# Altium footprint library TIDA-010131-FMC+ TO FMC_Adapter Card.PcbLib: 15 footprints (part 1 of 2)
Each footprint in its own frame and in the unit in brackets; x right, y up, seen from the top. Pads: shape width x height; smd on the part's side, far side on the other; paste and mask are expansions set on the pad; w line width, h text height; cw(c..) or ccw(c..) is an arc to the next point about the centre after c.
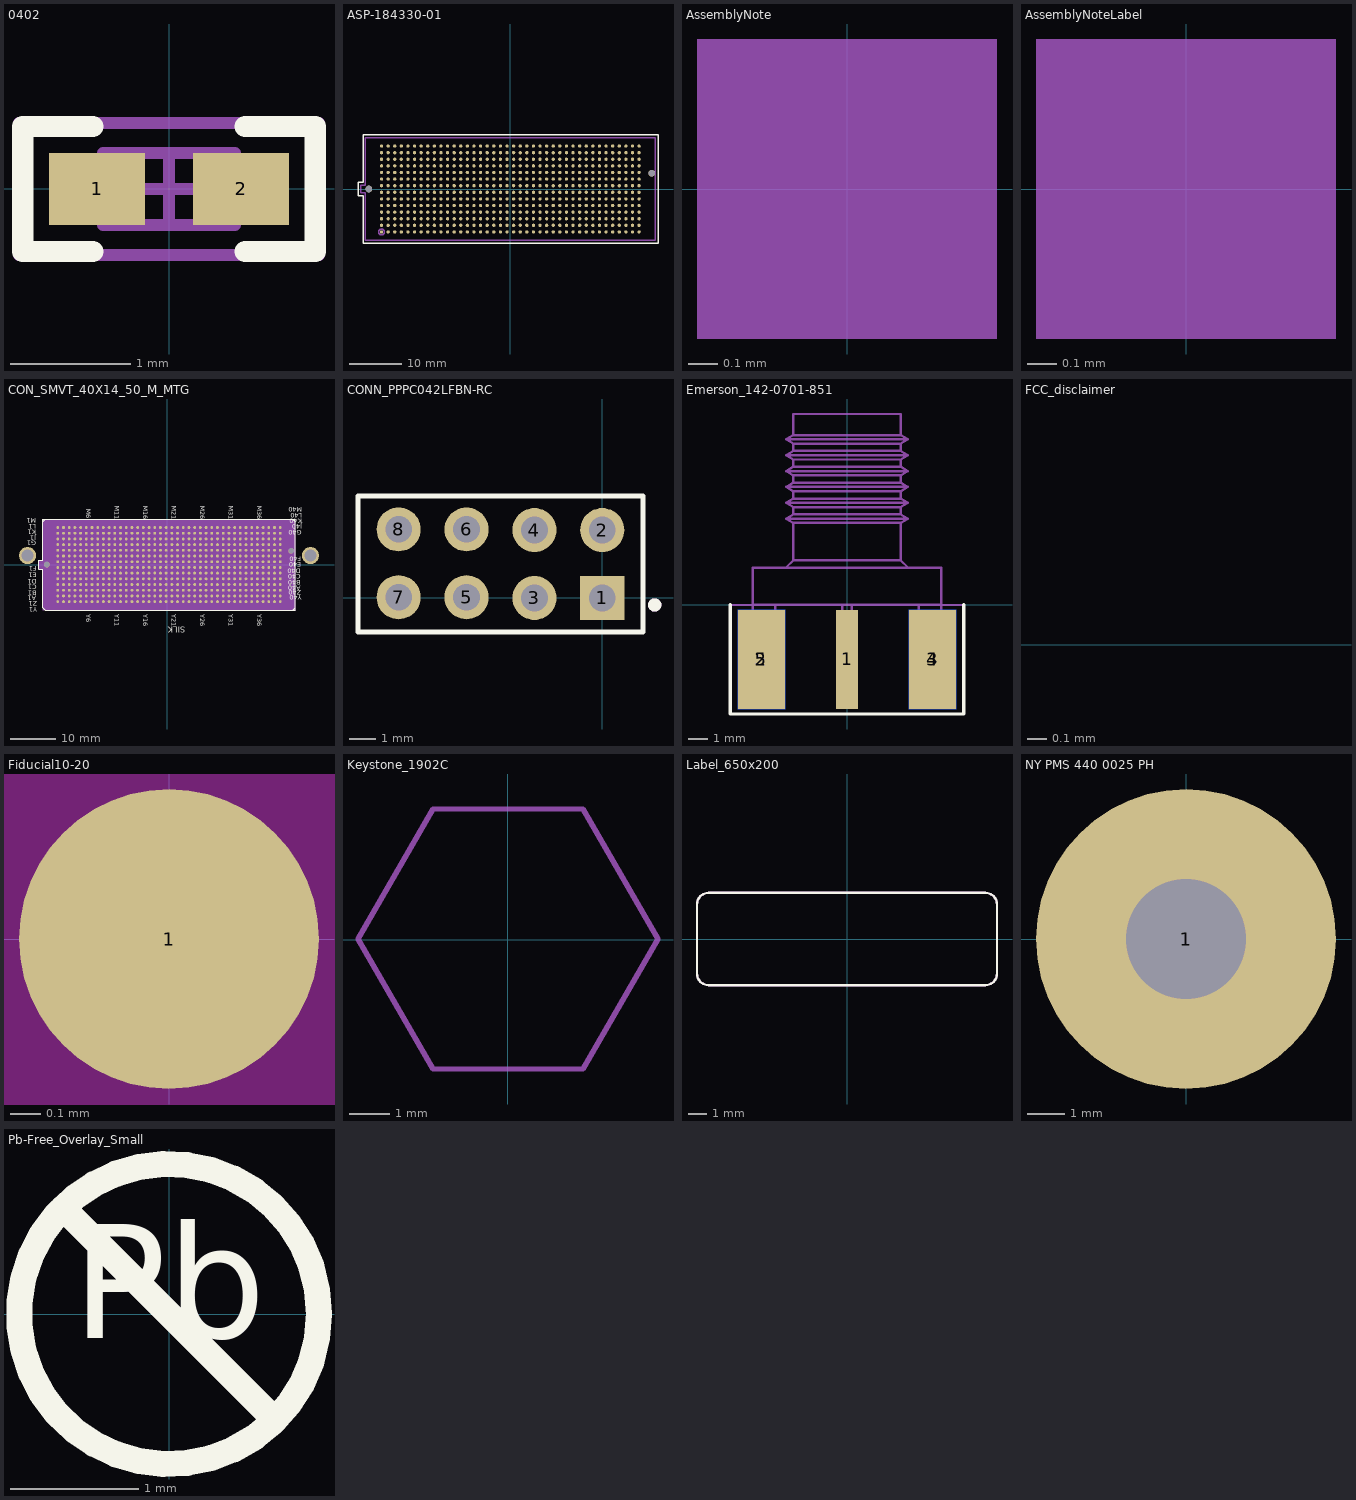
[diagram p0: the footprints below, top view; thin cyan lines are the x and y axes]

## 0402 [mm] "0402 from SM-752 data"
height 0.6
pads (2):
  rect 0.8x0.6 smd: 1(-0.6,0) 2(0.6,0)
Top Overlay:
  lines w0.178: -0.635,-0.521 -1.219,-0.521 -1.219,0.521 -0.635,0.521 ; 0.635,-0.521 1.219,-0.521 1.219,0.521 0.635,0.521
Mechanical 5:
  lines w0.1: -1.25,-0.55 1.25,-0.55 1.25,0.55 -1.25,0.55 -1.25,-0.55
  text ".Designator" at -1.117,-0.305 h0.61
Mechanical 13:
  lines w0.1: -0.35,-0.3 -0.35,0.3 ; 0.35,-0.3 0.35,0.3 ; -0.55,-0.3 -0.55,0.3 0.55,0.3 0.55,-0.3 -0.55,-0.3
Mechanical 15:
  lines w0.1: -0.3,0 0.3,0 ; 0,-0.3 0,0.3 ; -1.25,-0.55 -1.25,0.55 1.25,0.55 1.25,-0.55 -1.25,-0.55
3D body: height 0.6, standoff 0, extent -0.549,-0.299 -0.351,0.299
3D body: height 0.6, standoff 0, extent -0.349,-0.299 0.349,0.299
3D body: height 0.6, standoff 0, extent 0.351,-0.299 0.549,0.299

## ASP-184330-01 [mil]
height 375.2
pads (562):
  round 25 smd paste+5 mask+2: A1(-975,-225) A2(-925,-225) A3(-875,-225) A4(-825,-225) A5(-775,-225) A6(-725,-225) A7(-675,-225) A8(-625,-225) A9(-575,-225) A10(-525,-225) A11(-475,-225) A12(-425,-225) A13(-375,-225) A14(-325,-225) A15(-275,-225) A16(-225,-225) A17(-175,-225) A18(-125,-225) A19(-75,-225) A20(-25,-225) A21(25,-225) A22(75,-225) A23(125,-225) A24(175,-225) A25(225,-225) A26(275,-225) A27(325,-225) A28(375,-225) A29(425,-225) A30(475,-225) A31(525,-225) A32(575,-225) A33(625,-225) A34(675,-225) A35(725,-225) A36(775,-225) A37(825,-225) A38(875,-225) A39(925,-225) A40(975,-225) B1(-975,-175) B2(-925,-175) B3(-875,-175) B4(-825,-175) B5(-775,-175) B6(-725,-175) B7(-675,-175) B8(-625,-175) B9(-575,-175) B10(-525,-175) B11(-475,-175) B12(-425,-175) B13(-375,-175) B14(-325,-175) B15(-275,-175) B16(-225,-175) B17(-175,-175) B18(-125,-175) B19(-75,-175) B20(-25,-175) B21(25,-175) B22(75,-175) B23(125,-175) B24(175,-175) B25(225,-175) B26(275,-175) B27(325,-175) B28(375,-175) B29(425,-175) B30(475,-175) B31(525,-175) B32(575,-175) B33(625,-175) B34(675,-175) B35(725,-175) B36(775,-175) B37(825,-175) B38(875,-175) B39(925,-175) B40(975,-175) C1(-975,-125) C2(-925,-125) C3(-875,-125) C4(-825,-125) C5(-775,-125) C6(-725,-125) C7(-675,-125) C8(-625,-125) C9(-575,-125) C10(-525,-125) C11(-475,-125) C12(-425,-125) C13(-375,-125) C14(-325,-125) C15(-275,-125) C16(-225,-125) C17(-175,-125) C18(-125,-125) C19(-75,-125) C20(-25,-125) C21(25,-125) C22(75,-125) C23(125,-125) C24(175,-125) C25(225,-125) C26(275,-125) C27(325,-125) C28(375,-125) C29(425,-125) C30(475,-125) C31(525,-125) C32(575,-125) C33(625,-125) C34(675,-125) C35(725,-125) C36(775,-125) C37(825,-125) C38(875,-125) C39(925,-125) C40(975,-125) D1(-975,-75) D2(-925,-75) D3(-875,-75) D4(-825,-75) D5(-775,-75) D6(-725,-75) D7(-675,-75) D8(-625,-75) D9(-575,-75) D10(-525,-75) D11(-475,-75) D12(-425,-75) D13(-375,-75) D14(-325,-75) D15(-275,-75) D16(-225,-75) D17(-175,-75) D18(-125,-75) D19(-75,-75) D20(-25,-75) D21(25,-75) D22(75,-75) D23(125,-75) D24(175,-75) D25(225,-75) D26(275,-75) D27(325,-75) D28(375,-75) D29(425,-75) D30(475,-75) D31(525,-75) D32(575,-75) D33(625,-75) D34(675,-75) D35(725,-75) D36(775,-75) D37(825,-75) D38(875,-75) D39(925,-75) D40(975,-75) E1(-975,-25) E2(-925,-25) E3(-875,-25) E4(-825,-25) E5(-775,-25) E6(-725,-25) E7(-675,-25) E8(-625,-25) E9(-575,-25) E10(-525,-25) E11(-475,-25) E12(-425,-25) E13(-375,-25) E14(-325,-25) E15(-275,-25) E16(-225,-25) E17(-175,-25) E18(-125,-25) E19(-75,-25) E20(-25,-25) E21(25,-25) E22(75,-25) E23(125,-25) E24(175,-25) E25(225,-25) E26(275,-25) E27(325,-25) E28(375,-25) E29(425,-25) E30(475,-25) E31(525,-25) E32(575,-25) E33(625,-25) E34(675,-25) E35(725,-25) E36(775,-25) E37(825,-25) E38(875,-25) E39(925,-25) E40(975,-25) F1(-975,25) F2(-925,25) F3(-875,25) F4(-825,25) F5(-775,25) F6(-725,25) F7(-675,25) F8(-625,25) F9(-575,25) F10(-525,25) F11(-475,25) F12(-425,25) F13(-375,25) F14(-325,25) F15(-275,25) F16(-225,25) F17(-175,25) F18(-125,25) F19(-75,25) F20(-25,25) F21(25,25) F22(75,25) F23(125,25) F24(175,25) F25(225,25) F26(275,25) F27(325,25) F28(375,25) F29(425,25) F30(475,25) F31(525,25) F32(575,25) F33(625,25) F34(675,25) F35(725,25) F36(775,25) F37(825,25) F38(875,25) F39(925,25) F40(975,25) G1(-975,75) G2(-925,75) G3(-875,75) G4(-825,75) G5(-775,75) G6(-725,75) G7(-675,75) G8(-625,75) G9(-575,75) G10(-525,75) G11(-475,75) G12(-425,75) G13(-375,75) G14(-325,75) G15(-275,75) G16(-225,75) G17(-175,75) G18(-125,75) G19(-75,75) G20(-25,75) G21(25,75) G22(75,75) G23(125,75) G24(175,75) G25(225,75) G26(275,75) G27(325,75) G28(375,75) G29(425,75) G30(475,75) G31(525,75) G32(575,75) G33(625,75) G34(675,75) G35(725,75) G36(775,75) G37(825,75) G38(875,75) G39(925,75) G40(975,75) H1(-975,125) H2(-925,125) H3(-875,125) H4(-825,125) H5(-775,125) H6(-725,125) H7(-675,125) H8(-625,125) H9(-575,125) H10(-525,125) H11(-475,125) H12(-425,125) H13(-375,125) H14(-325,125) H15(-275,125) H16(-225,125) H17(-175,125) H18(-125,125) H19(-75,125) H20(-25,125) H21(25,125) H22(75,125) H23(125,125) H24(175,125) H25(225,125) H26(275,125) H27(325,125) H28(375,125) H29(425,125) H30(475,125) H31(525,125) H32(575,125) H33(625,125) H34(675,125) H35(725,125) H36(775,125) H37(825,125) H38(875,125) H39(925,125) H40(975,125) J1(-975,175) J2(-925,175) J3(-875,175) J4(-825,175) J5(-775,175) J6(-725,175) J7(-675,175) J8(-625,175) J9(-575,175) J10(-525,175) J11(-475,175) J12(-425,175) J13(-375,175) J14(-325,175) J15(-275,175) J16(-225,175) J17(-175,175) J18(-125,175) J19(-75,175) J20(-25,175) J21(25,175) J22(75,175) J23(125,175) J24(175,175) J25(225,175) J26(275,175) J27(325,175) J28(375,175) J29(425,175) J30(475,175) J31(525,175) J32(575,175) J33(625,175) J34(675,175) J35(725,175) J36(775,175) J37(825,175) J38(875,175) J39(925,175) J40(975,175) K1(-975,225) K2(-925,225) K3(-875,225) K4(-825,225) K5(-775,225) K6(-725,225) K7(-675,225) K8(-625,225) K9(-575,225) K10(-525,225) K11(-475,225) K12(-425,225) K13(-375,225) K14(-325,225) K15(-275,225) K16(-225,225) K17(-175,225) K18(-125,225) K19(-75,225) K20(-25,225) K21(25,225) K22(75,225) K23(125,225) K24(175,225) K25(225,225) K26(275,225) K27(325,225) K28(375,225) K29(425,225) K30(475,225) K31(525,225) K32(575,225) K33(625,225) K34(675,225) K35(725,225) K36(775,225) K37(825,225) K38(875,225) K39(925,225) K40(975,225) L1(-975,275) L2(-925,275) L3(-875,275) L4(-825,275) L5(-775,275) L6(-725,275) L7(-675,275) L8(-625,275) L9(-575,275) L10(-525,275) L11(-475,275) L12(-425,275) L13(-375,275) L14(-325,275) L15(-275,275) L16(-225,275) L17(-175,275) L18(-125,275) L19(-75,275) L20(-25,275) L21(25,275) L22(75,275) L23(125,275) L24(175,275) L25(225,275) L26(275,275) L27(325,275) L28(375,275) L29(425,275) L30(475,275) L31(525,275) L32(575,275) L33(625,275) L34(675,275) L35(725,275) L36(775,275) L37(825,275) L38(875,275) L39(925,275) L40(975,275) M1(-975,325) M2(-925,325) M3(-875,325) M4(-825,325) M5(-775,325) M6(-725,325) M7(-675,325) M8(-625,325) M9(-575,325) M10(-525,325) M11(-475,325) M12(-425,325) M13(-375,325) M14(-325,325) M15(-275,325) M16(-225,325) M17(-175,325) M18(-125,325) M19(-75,325) M20(-25,325) M21(25,325) M22(75,325) M23(125,325) M24(175,325) M25(225,325) M26(275,325) M27(325,325) M28(375,325) M29(425,325) M30(475,325) M31(525,325) M32(575,325) M33(625,325) M34(675,325) M35(725,325) M36(775,325) M37(825,325) M38(875,325) M39(925,325) M40(975,325) Y1(-975,-325) Y2(-925,-325) Y3(-875,-325) Y4(-825,-325) Y5(-775,-325) Y6(-725,-325) Y7(-675,-325) Y8(-625,-325) Y9(-575,-325) Y10(-525,-325) Y11(-475,-325) Y12(-425,-325) Y13(-375,-325) Y14(-325,-325) Y15(-275,-325) Y16(-225,-325) Y17(-175,-325) Y18(-125,-325) Y19(-75,-325) Y20(-25,-325) Y21(25,-325) Y22(75,-325) Y23(125,-325) Y24(175,-325) Y25(225,-325) Y26(275,-325) Y27(325,-325) Y28(375,-325) Y29(425,-325) Y30(475,-325) Y31(525,-325) Y32(575,-325) Y33(625,-325) Y34(675,-325) Y35(725,-325) Y36(775,-325) Y37(825,-325) Y38(875,-325) Y39(925,-325) Y40(975,-325) Z1(-975,-275) Z2(-925,-275) Z3(-875,-275) Z4(-825,-275) Z5(-775,-275) Z6(-725,-275) Z7(-675,-275) Z8(-625,-275) Z9(-575,-275) Z10(-525,-275) Z11(-475,-275) Z12(-425,-275) Z13(-375,-275) Z14(-325,-275) Z15(-275,-275) Z16(-225,-275) Z17(-175,-275) Z18(-125,-275) Z19(-75,-275) Z20(-25,-275) Z21(25,-275) Z22(75,-275) Z23(125,-275) Z24(175,-275) Z25(225,-275) Z26(275,-275) Z27(325,-275) Z28(375,-275) Z29(425,-275) Z30(475,-275) Z31(525,-275) Z32(575,-275) Z33(625,-275) Z34(675,-275) Z35(725,-275) Z36(775,-275) Z37(825,-275) Z38(875,-275) Z39(925,-275) Z40(975,-275)
  round 50 hole 50 unplated mask+10: MH1(-1070.5,0) MH2(1070.5,120)
Top Overlay:
  lines w10: -1153,-50 -1115,-50 -1115,-409 1118,-409 1118,409 -1115,409 -1115,50 -1153,50 -1153,-50
Mechanical 5:
  circle w10: c-975,-325 r22.36
  lines w10: -1133,-30 -1098,-30 -1098,-389 1098,-389 1098,389 -1098,389 -1098,30 -1133,30 -1133,-30
  text "J1" at 52.11,-0.07 h20

## AssemblyNote [mil] "Assembly Note"
Mechanical 5:
  rectangle: -20,-20 20,20
  text ".Designator" at -165,-20 h25

## AssemblyNoteLabel [mil] "Assembly Note for PCB Labels"
Mechanical 5:
  rectangle: -20,-20 20,20
  text ".Designator" at -165,-20 h25
  text "Install label in silkscreened box after final wash.  Text shall be 8 pt font.  Text shall be per the Label Table in the PDF schematic." at 45,-20 h25

## CON_SMVT_40X14_50_M_MTG [mil] "CON_SMVT_40X14_50_M_MTG"
pads (564):
  round 150 hole 106: " "(-1222.5,79) " "(1257.5,79)
  round 50 hole 50: " "(-1053,0) " "(1088,120)
  round 25 smd: A1(-957.5,-225) A2(-907.5,-225) A3(-857.5,-225) A4(-807.5,-225) A5(-757.5,-225) A6(-707.5,-225) A7(-657.5,-225) A8(-607.5,-225) A9(-557.5,-225) A10(-507.5,-225) A11(-457.5,-225) A12(-407.5,-225) A13(-357.5,-225) A14(-307.5,-225) A15(-257.5,-225) A16(-207.5,-225) A17(-157.5,-225) A18(-107.5,-225) A19(-57.5,-225) A20(-7.5,-225) A21(42.5,-225) A22(92.5,-225) A23(142.5,-225) A24(192.5,-225) A25(242.5,-225) A26(292.5,-225) A27(342.5,-225) A28(392.5,-225) A29(442.5,-225) A30(492.5,-225) A31(542.5,-225) A32(592.5,-225) A33(642.5,-225) A34(692.5,-225) A35(742.5,-225) A36(792.5,-225) A37(842.5,-225) A38(892.5,-225) A39(942.5,-225) A40(992.5,-225) B1(-957.5,-175) B2(-907.5,-175) B3(-857.5,-175) B4(-807.5,-175) B5(-757.5,-175) B6(-707.5,-175) B7(-657.5,-175) B8(-607.5,-175) B9(-557.5,-175) B10(-507.5,-175) B11(-457.5,-175) B12(-407.5,-175) B13(-357.5,-175) B14(-307.5,-175) B15(-257.5,-175) B16(-207.5,-175) B17(-157.5,-175) B18(-107.5,-175) B19(-57.5,-175) B20(-7.5,-175) B21(42.5,-175) B22(92.5,-175) B23(142.5,-175) B24(192.5,-175) B25(242.5,-175) B26(292.5,-175) B27(342.5,-175) B28(392.5,-175) B29(442.5,-175) B30(492.5,-175) B31(542.5,-175) B32(592.5,-175) B33(642.5,-175) B34(692.5,-175) B35(742.5,-175) B36(792.5,-175) B37(842.5,-175) B38(892.5,-175) B39(942.5,-175) B40(992.5,-175) C1(-957.5,-125) C2(-907.5,-125) C3(-857.5,-125) C4(-807.5,-125) C5(-757.5,-125) C6(-707.5,-125) C7(-657.5,-125) C8(-607.5,-125) C9(-557.5,-125) C10(-507.5,-125) C11(-457.5,-125) C12(-407.5,-125) C13(-357.5,-125) C14(-307.5,-125) C15(-257.5,-125) C16(-207.5,-125) C17(-157.5,-125) C18(-107.5,-125) C19(-57.5,-125) C20(-7.5,-125) C21(42.5,-125) C22(92.5,-125) C23(142.5,-125) C24(192.5,-125) C25(242.5,-125) C26(292.5,-125) C27(342.5,-125) C28(392.5,-125) C29(442.5,-125) C30(492.5,-125) C31(542.5,-125) C32(592.5,-125) C33(642.5,-125) C34(692.5,-125) C35(742.5,-125) C36(792.5,-125) C37(842.5,-125) C38(892.5,-125) C39(942.5,-125) C40(992.5,-125) D1(-957.5,-75) D2(-907.5,-75) D3(-857.5,-75) D4(-807.5,-75) D5(-757.5,-75) D6(-707.5,-75) D7(-657.5,-75) D8(-607.5,-75) D9(-557.5,-75) D10(-507.5,-75) D11(-457.5,-75) D12(-407.5,-75) D13(-357.5,-75) D14(-307.5,-75) D15(-257.5,-75) D16(-207.5,-75) D17(-157.5,-75) D18(-107.5,-75) D19(-57.5,-75) D20(-7.5,-75) D21(42.5,-75) D22(92.5,-75) D23(142.5,-75) D24(192.5,-75) D25(242.5,-75) D26(292.5,-75) D27(342.5,-75) D28(392.5,-75) D29(442.5,-75) D30(492.5,-75) D31(542.5,-75) D32(592.5,-75) D33(642.5,-75) D34(692.5,-75) D35(742.5,-75) D36(792.5,-75) D37(842.5,-75) D38(892.5,-75) D39(942.5,-75) D40(992.5,-75) E1(-957.5,-25) E2(-907.5,-25) E3(-857.5,-25) E4(-807.5,-25) E5(-757.5,-25) E6(-707.5,-25) E7(-657.5,-25) E8(-607.5,-25) E9(-557.5,-25) E10(-507.5,-25) E11(-457.5,-25) E12(-407.5,-25) E13(-357.5,-25) E14(-307.5,-25) E15(-257.5,-25) E16(-207.5,-25) E17(-157.5,-25) E18(-107.5,-25) E19(-57.5,-25) E20(-7.5,-25) E21(42.5,-25) E22(92.5,-25) E23(142.5,-25) E24(192.5,-25) E25(242.5,-25) E26(292.5,-25) E27(342.5,-25) E28(392.5,-25) E29(442.5,-25) E30(492.5,-25) E31(542.5,-25) E32(592.5,-25) E33(642.5,-25) E34(692.5,-25) E35(742.5,-25) E36(792.5,-25) E37(842.5,-25) E38(892.5,-25) E39(942.5,-25) E40(992.5,-25) F1(-957.5,25) F2(-907.5,25) F3(-857.5,25) F4(-807.5,25) F5(-757.5,25) F6(-707.5,25) F7(-657.5,25) F8(-607.5,25) F9(-557.5,25) F10(-507.5,25) F11(-457.5,25) F12(-407.5,25) F13(-357.5,25) F14(-307.5,25) F15(-257.5,25) F16(-207.5,25) F17(-157.5,25) F18(-107.5,25) F19(-57.5,25) F20(-7.5,25) F21(42.5,25) F22(92.5,25) F23(142.5,25) F24(192.5,25) F25(242.5,25) F26(292.5,25) F27(342.5,25) F28(392.5,25) F29(442.5,25) F30(492.5,25) F31(542.5,25) F32(592.5,25) F33(642.5,25) F34(692.5,25) F35(742.5,25) F36(792.5,25) F37(842.5,25) F38(892.5,25) F39(942.5,25) F40(992.5,25) G1(-957.5,75) G2(-907.5,75) G3(-857.5,75) G4(-807.5,75) G5(-757.5,75) G6(-707.5,75) G7(-657.5,75) G8(-607.5,75) G9(-557.5,75) G10(-507.5,75) G11(-457.5,75) G12(-407.5,75) G13(-357.5,75) G14(-307.5,75) G15(-257.5,75) G16(-207.5,75) G17(-157.5,75) G18(-107.5,75) G19(-57.5,75) G20(-7.5,75) G21(42.5,75) G22(92.5,75) G23(142.5,75) G24(192.5,75) G25(242.5,75) G26(292.5,75) G27(342.5,75) G28(392.5,75) G29(442.5,75) G30(492.5,75) G31(542.5,75) G32(592.5,75) G33(642.5,75) G34(692.5,75) G35(742.5,75) G36(792.5,75) G37(842.5,75) G38(892.5,75) G39(942.5,75) G40(992.5,75) H1(-957.5,125) H2(-907.5,125) H3(-857.5,125) H4(-807.5,125) H5(-757.5,125) H6(-707.5,125) H7(-657.5,125) H8(-607.5,125) H9(-557.5,125) H10(-507.5,125) H11(-457.5,125) H12(-407.5,125) H13(-357.5,125) H14(-307.5,125) H15(-257.5,125) H16(-207.5,125) H17(-157.5,125) H18(-107.5,125) H19(-57.5,125) H20(-7.5,125) H21(42.5,125) H22(92.5,125) H23(142.5,125) H24(192.5,125) H25(242.5,125) H26(292.5,125) H27(342.5,125) H28(392.5,125) H29(442.5,125) H30(492.5,125) H31(542.5,125) H32(592.5,125) H33(642.5,125) H34(692.5,125) H35(742.5,125) H36(792.5,125) H37(842.5,125) H38(892.5,125) H39(942.5,125) H40(992.5,125) J1(-957.5,175) J2(-907.5,175) J3(-857.5,175) J4(-807.5,175) J5(-757.5,175) J6(-707.5,175) J7(-657.5,175) J8(-607.5,175) J9(-557.5,175) J10(-507.5,175) J11(-457.5,175) J12(-407.5,175) J13(-357.5,175) J14(-307.5,175) J15(-257.5,175) J16(-207.5,175) J17(-157.5,175) J18(-107.5,175) J19(-57.5,175) J20(-7.5,175) J21(42.5,175) J22(92.5,175) J23(142.5,175) J24(192.5,175) J25(242.5,175) J26(292.5,175) J27(342.5,175) J28(392.5,175) J29(442.5,175) J30(492.5,175) J31(542.5,175) J32(592.5,175) J33(642.5,175) J34(692.5,175) J35(742.5,175) J36(792.5,175) J37(842.5,175) J38(892.5,175) J39(942.5,175) J40(992.5,175) K1(-957.5,225) K2(-907.5,225) K3(-857.5,225) K4(-807.5,225) K5(-757.5,225) K6(-707.5,225) K7(-657.5,225) K8(-607.5,225) K9(-557.5,225) K10(-507.5,225) K11(-457.5,225) K12(-407.5,225) K13(-357.5,225) K14(-307.5,225) K15(-257.5,225) K16(-207.5,225) K17(-157.5,225) K18(-107.5,225) K19(-57.5,225) K20(-7.5,225) K21(42.5,225) K22(92.5,225) K23(142.5,225) K24(192.5,225) K25(242.5,225) K26(292.5,225) K27(342.5,225) K28(392.5,225) K29(442.5,225) K30(492.5,225) K31(542.5,225) K32(592.5,225) K33(642.5,225) K34(692.5,225) K35(742.5,225) K36(792.5,225) K37(842.5,225) K38(892.5,225) K39(942.5,225) K40(992.5,225) L1(-957.5,275) L2(-907.5,275) L3(-857.5,275) L4(-807.5,275) L5(-757.5,275) L6(-707.5,275) L7(-657.5,275) L8(-607.5,275) L9(-557.5,275) L10(-507.5,275) L11(-457.5,275) L12(-407.5,275) L13(-357.5,275) L14(-307.5,275) L15(-257.5,275) L16(-207.5,275) L17(-157.5,275) L18(-107.5,275) L19(-57.5,275) L20(-7.5,275) L21(42.5,275) L22(92.5,275) L23(142.5,275) L24(192.5,275) L25(242.5,275) L26(292.5,275) L27(342.5,275) L28(392.5,275) L29(442.5,275) L30(492.5,275) L31(542.5,275) L32(592.5,275) L33(642.5,275) L34(692.5,275) L35(742.5,275) L36(792.5,275) L37(842.5,275) L38(892.5,275) L39(942.5,275) L40(992.5,275) M1(-957.5,325) M2(-907.5,325) M3(-857.5,325) M4(-807.5,325) M5(-757.5,325) M6(-707.5,325) M7(-657.5,325) M8(-607.5,325) M9(-557.5,325) M10(-507.5,325) M11(-457.5,325) M12(-407.5,325) M13(-357.5,325) M14(-307.5,325) M15(-257.5,325) M16(-207.5,325) M17(-157.5,325) M18(-107.5,325) M19(-57.5,325) M20(-7.5,325) M21(42.5,325) M22(92.5,325) M23(142.5,325) M24(192.5,325) M25(242.5,325) M26(292.5,325) M27(342.5,325) M28(392.5,325) M29(442.5,325) M30(492.5,325) M31(542.5,325) M32(592.5,325) M33(642.5,325) M34(692.5,325) M35(742.5,325) M36(792.5,325) M37(842.5,325) M38(892.5,325) M39(942.5,325) M40(992.5,325) Y1(-957.5,-325) Y2(-907.5,-325) Y3(-857.5,-325) Y4(-807.5,-325) Y5(-757.5,-325) Y6(-707.5,-325) Y7(-657.5,-325) Y8(-607.5,-325) Y9(-557.5,-325) Y10(-507.5,-325) Y11(-457.5,-325) Y12(-407.5,-325) Y13(-357.5,-325) Y14(-307.5,-325) Y15(-257.5,-325) Y16(-207.5,-325) Y17(-157.5,-325) Y18(-107.5,-325) Y19(-57.5,-325) Y20(-7.5,-325) Y21(42.5,-325) Y22(92.5,-325) Y23(142.5,-325) Y24(192.5,-325) Y25(242.5,-325) Y26(292.5,-325) Y27(342.5,-325) Y28(392.5,-325) Y29(442.5,-325) Y30(492.5,-325) Y31(542.5,-325) Y32(592.5,-325) Y33(642.5,-325) Y34(692.5,-325) Y35(742.5,-325) Y36(792.5,-325) Y37(842.5,-325) Y38(892.5,-325) Y39(942.5,-325) Y40(992.5,-325) Z1(-957.5,-275) Z2(-907.5,-275) Z3(-857.5,-275) Z4(-807.5,-275) Z5(-757.5,-275) Z6(-707.5,-275) Z7(-657.5,-275) Z8(-607.5,-275) Z9(-557.5,-275) Z10(-507.5,-275) Z11(-457.5,-275) Z12(-407.5,-275) Z13(-357.5,-275) Z14(-307.5,-275) Z15(-257.5,-275) Z16(-207.5,-275) Z17(-157.5,-275) Z18(-107.5,-275) Z19(-57.5,-275) Z20(-7.5,-275) Z21(42.5,-275) Z22(92.5,-275) Z23(142.5,-275) Z24(192.5,-275) Z25(242.5,-275) Z26(292.5,-275) Z27(342.5,-275) Z28(392.5,-275) Z29(442.5,-275) Z30(492.5,-275) Z31(542.5,-275) Z32(592.5,-275) Z33(642.5,-275) Z34(692.5,-275) Z35(742.5,-275) Z36(792.5,-275) Z37(842.5,-275) Z38(892.5,-275) Z39(942.5,-275) Z40(992.5,-275)
Top Overlay:
  lines w10: -1090.5,377 -1068.5,399 ; 1103.5,-399 1125.5,-377 ; 1103.5,399 1125.5,377 ; -1125.5,-40 -1125.5,40 -1090.5,40 -1090.5,399 1125.5,399 1125.5,-399 -1068.5,-399 -1090.5,-377 -1090.5,-40 -1125.5,-40
  text "D40" at 1173.5,-37 h40
  text "M36" at 792.5,515 h40
  text "M31" at 542.5,515 h40
  text "M26" at 292.5,515 h40
  text "M21" at 42.5,515 h40
  text "M16" at -207.5,515 h40
  text "M11" at -457.5,515 h40
  text "M6" at -707.5,490 h40
  text "Y36" at 792.5,-435 h40
  text "Y31" at 542.5,-435 h40
  text "Y26" at 292.5,-435 h40
  text "Y21" at 42.5,-435 h40
  text "Y16" at -207.5,-435 h40
  text "Y11" at -457.5,-435 h40
  text "D1" at -1142.5,-128 h40
  text "SILK" at 158.5,-545 h50
  text "C1" at -1142.5,-178 h40
  text "Y6" at -707.5,-435 h40
  text "C40" at 1173.5,-87 h40
  text "B1" at -1142.5,-228 h40
  text "Y1" at -1136.5,-374.33 h40
  text "B40" at 1173.5,-137 h40
  text "Y40" at 1179.5,-269.33 h40
  text "M40" at 1183.5,502 h40
  text "M1" at -1145.5,404 h40
  text "L40" at 1183.5,452 h40
  text "L1" at -1145.5,354 h40
  text "K40" at 1183.5,402 h40
  text "K1" at -1145.5,304 h40
  text "J40" at 1183.5,352 h40
  text "J1" at -1145.5,254 h40
  text "E1" at -1140.5,-71.33 h40
  text "E40" at 1176.5,19.67 h40
  text "F40" at 1178.5,68 h40
  text "G40" at 1180.5,301.67 h40
  text "F1" at -1140.5,-14 h40
  text "G1" at -1144.5,207.67 h40
  text "Z40" at 1177.5,-227 h40
  text "Z1" at -1136.5,-323 h40
  text "A40" at 1172.5,-185 h40
  text "A1" at -1144.5,-273 h40
Bottom Overlay:
  text "M1" at -1057.5,350 h40
  text "M40" at 1042.5,350 h40
  text "Y1" at -1057.5,-350 h40
  text "Y40" at 1019.5,-352.33 h40
Mechanical 5:
  lines w1: -1080.5,-367 -1058.5,-389 ; -1080.5,367 -1058.5,389 ; 1093.5,-389 1115.5,-367 ; 1093.5,389 1115.5,367 ; -1115.5,-30 -1115.5,30 -1080.5,30 -1080.5,389 1115.5,389 1115.5,-389 -1080.5,-389 -1080.5,-30 -1115.5,-30
  text ".Designator" at 79.5,24 h63
Mechanical 16:
  region: 1125.5,-399 -1090.5,-399 -1090.5,-40 -1125.5,-40 -1125.5,40 -1090.5,40 -1090.5,399 1125.5,399
Mechanical 27:
  text "Z21" at 29.5,-221.81 h20.08
  text "G7" at -657.5,91.06 h20.08
  text "Z20" at -20.5,-221.81 h20.08
  text "D5" at -757.5,-58.94 h20.08
  text "D4" at -807.5,-58.94 h20.08
  text "G6" at -707.5,91.06 h20.08
  text "Y14" at -320.5,-271.81 h20.08
  text "Y15" at -270.5,-271.81 h20.08
  text "Y18" at -120.5,-271.81 h20.08
  text "Y11" at -470.5,-271.81 h20.08
  text "Z12" at -420.5,-221.81 h20.08
  text "Z1" at -970.5,-237.87 h20.08
  text "Z17" at -170.5,-221.81 h20.08
  text "Y23" at 129.5,-271.81 h20.08
  text "Y22" at 79.5,-271.81 h20.08
  text "Z13" at -370.5,-221.81 h20.08
  text "Z16" at -220.5,-221.81 h20.08
  text "Y19" at -70.5,-271.81 h20.08
  text "Y10" at -520.5,-271.81 h20.08
  text "C34" at 692.5,-100.9 h20.08
  text "D40" at 992.5,-50.9 h20.08
  text "D36" at 792.5,-50.9 h20.08
  text "D38" at 892.5,-50.9 h20.08
  text "C39" at 942.5,-100.9 h20.08
  text "F40" at 992.5,49.1 h20.08
  text "E39" at 942.5,-0.9 h20.08
  text "G39" at 942.5,99.1 h20.08
  text "H40" at 992.5,149.1 h20.08
  text "B9" at -557.5,-158.94 h20.08
  text "B4" at -807.5,-158.94 h20.08
  text "D35" at 742.5,-50.9 h20.08
  text "B5" at -757.5,-158.94 h20.08
  text "D31" at 542.5,-50.9 h20.08
  text "D1" at -957.5,-58.94 h20.08
  text "C31" at 542.5,-100.9 h20.08
  text "C30" at 492.5,-100.9 h20.08
  text "D32" at 592.5,-50.9 h20.08
  text "D30" at 492.5,-50.9 h20.08
  text "B8" at -607.5,-158.94 h20.08
  text "F1" at -957.5,41.06 h20.08
  text "D26" at 292.5,-50.9 h20.08
  text "C37" at 842.5,-100.9 h20.08
  text "C35" at 742.5,-100.9 h20.08
  text "G12" at -407.5,99.1 h20.08
  text "G27" at 342.5,99.1 h20.08
  text "H31" at 542.5,149.1 h20.08
  text "G13" at -357.5,99.1 h20.08
  text "H2" at -907.5,141.06 h20.08
  text "K40" at 992.5,249.1 h20.08
  text "J39" at 942.5,199.1 h20.08
  text "J15" at -257.5,199.1 h20.08
  text "A15" at -257.5,-200.9 h20.08
  text "B17" at -157.5,-150.9 h20.08
  text "B16" at -207.5,-150.9 h20.08
  text "A7" at -657.5,-208.94 h20.08
  text "A6" at -707.5,-208.94 h20.08
  text "A3" at -857.5,-208.94 h20.08
  text "A2" at -907.5,-208.94 h20.08
  text "A19" at -57.5,-200.9 h20.08
  text "A18" at -107.5,-200.9 h20.08
  text "A14" at -307.5,-200.9 h20.08
  text "B13" at -357.5,-150.9 h20.08
  text "B12" at -407.5,-150.9 h20.08
  text "C7" at -657.5,-108.94 h20.08
  text "C6" at -707.5,-108.94 h20.08
  text "A11" at -457.5,-200.9 h20.08
  text "A10" at -507.5,-200.9 h20.08
  text "G10" at -507.5,99.1 h20.08
  text "G9" at -557.5,91.06 h20.08
  text "B11" at -457.5,-150.9 h20.08
  text "B10" at -507.5,-150.9 h20.08
  text "B7" at -657.5,-158.94 h20.08
  text "B6" at -707.5,-158.94 h20.08
  text "B3" at -857.5,-158.94 h20.08
  text "B2" at -907.5,-158.94 h20.08
  text "B15" at -257.5,-150.9 h20.08
  text "B14" at -307.5,-150.9 h20.08
  text "B19" at -57.5,-150.9 h20.08
  text "B18" at -107.5,-150.9 h20.08
  text "B27" at 342.5,-150.9 h20.08
  text "B26" at 292.5,-150.9 h20.08
  text "B23" at 142.5,-150.9 h20.08
  text "B22" at 92.5,-150.9 h20.08
  text "B31" at 542.5,-150.9 h20.08
  text "B30" at 492.5,-150.9 h20.08
  text "B35" at 742.5,-150.9 h20.08
  text "B34" at 692.5,-150.9 h20.08
  text "B39" at 942.5,-150.9 h20.08
  text "B38" at 892.5,-150.9 h20.08
  text "F39" at 942.5,49.1 h20.08
  text "F27" at 342.5,49.1 h20.08
  text "F15" at -257.5,49.1 h20.08
  text "F36" at 792.5,49.1 h20.08
  text "F24" at 192.5,49.1 h20.08
  text "F3" at -857.5,41.06 h20.08
  text "F6" at -707.5,41.06 h20.08
  text "F9" at -557.5,41.06 h20.08
  text "F18" at -107.5,49.1 h20.08
  text "F21" at 42.5,49.1 h20.08
  text "F2" at -907.5,41.06 h20.08
  text "C38" at 892.5,-100.9 h20.08
  text "C36" at 792.5,-100.9 h20.08
  text "C33" at 642.5,-100.9 h20.08
  text "C32" at 592.5,-100.9 h20.08
  text "C29" at 442.5,-100.9 h20.08
  text "C28" at 392.5,-100.9 h20.08
  text "C25" at 242.5,-100.9 h20.08
  text "C24" at 192.5,-100.9 h20.08
  text "C21" at 42.5,-100.9 h20.08
  text "C20" at -7.5,-100.9 h20.08
  text "C17" at -157.5,-100.9 h20.08
  text "C16" at -207.5,-100.9 h20.08
  text "C12" at -407.5,-100.9 h20.08
  text "C9" at -557.5,-108.94 h20.08
  text "C8" at -607.5,-108.94 h20.08
  text "C5" at -757.5,-108.94 h20.08
  text "C4" at -807.5,-108.94 h20.08
  text "C1" at -957.5,-108.94 h20.08
  text "C40" at 992.5,-100.9 h20.08
  text "D39" at 942.5,-50.9 h20.08
  text "D2" at -907.5,-58.94 h20.08
  text "D37" at 842.5,-50.9 h20.08
  text "D28" at 392.5,-50.9 h20.08
  text "D25" at 242.5,-50.9 h20.08
  text "D22" at 92.5,-50.9 h20.08
  text "D19" at -57.5,-50.9 h20.08
  text "D16" at -207.5,-50.9 h20.08
  text "D10" at -507.5,-50.9 h20.08
  text "D7" at -657.5,-58.94 h20.08
  text "D6" at -707.5,-58.94 h20.08
  text "D3" at -857.5,-58.94 h20.08
  text "E40" at 992.5,-0.9 h20.08
  text "E38" at 892.5,-0.9 h20.08
  text "E35" at 742.5,-0.9 h20.08
  text "E29" at 442.5,-0.9 h20.08
  text "E26" at 292.5,-0.9 h20.08
  text "E23" at 142.5,-0.9 h20.08
  text "E20" at -7.5,-0.9 h20.08
  text "E17" at -157.5,-0.9 h20.08
  text "E14" at -307.5,-0.9 h20.08
  text "E11" at -457.5,-0.9 h20.08
  text "E8" at -607.5,-8.94 h20.08
  text "E5" at -757.5,-8.94 h20.08
  text "E4" at -807.5,-8.94 h20.08
  text "E1" at -957.5,-8.94 h20.08
  text "A5" at -757.5,-208.94 h20.08
  text "A9" at -557.5,-208.94 h20.08
  text "A16" at -207.5,-200.9 h20.08
  text "A17" at -157.5,-200.9 h20.08
  text "A20" at -7.5,-200.9 h20.08
  text "A21" at 42.5,-200.9 h20.08
  text "A24" at 192.5,-200.9 h20.08
  text "A25" at 242.5,-200.9 h20.08
  text "A33" at 642.5,-200.9 h20.08
  text "A32" at 592.5,-200.9 h20.08
  text "A28" at 392.5,-200.9 h20.08
  text "A29" at 442.5,-200.9 h20.08
  text "A40" at 992.5,-200.9 h20.08
  text "A36" at 792.5,-200.9 h20.08
  text "A37" at 842.5,-200.9 h20.08
  text "A4" at -807.5,-208.94 h20.08
  text "A8" at -607.5,-208.94 h20.08
  text "A1" at -957.5,-208.94 h20.08
  text "G1" at -957.5,91.06 h20.08
  text "G5" at -757.5,91.06 h20.08
  text "J4" at -807.5,191.06 h20.08
  text "J1" at -957.5,191.06 h20.08
  text "J40" at 992.5,199.1 h20.08
  text "J38" at 892.5,199.1 h20.08
  text "J35" at 742.5,199.1 h20.08
  text "J29" at 442.5,199.1 h20.08
  text "J26" at 292.5,199.1 h20.08
  text "J23" at 142.5,199.1 h20.08
  text "J20" at -7.5,199.1 h20.08
  text "J17" at -157.5,199.1 h20.08
  text "J14" at -307.5,199.1 h20.08
  text "J11" at -457.5,199.1 h20.08
  text "J8" at -607.5,191.06 h20.08
  text "J5" at -757.5,191.06 h20.08
  text "H3" at -857.5,141.06 h20.08
  text "H39" at 942.5,149.1 h20.08
  text "H36" at 792.5,149.1 h20.08
  text "H27" at 342.5,149.1 h20.08
  text "H24" at 192.5,149.1 h20.08
  text "H21" at 42.5,149.1 h20.08
  text "H18" at -107.5,149.1 h20.08
  text "H15" at -257.5,149.1 h20.08
  text "H6" at -707.5,141.06 h20.08
  text "G38" at 892.5,99.1 h20.08
  text "G35" at 742.5,99.1 h20.08
  text "G29" at 442.5,99.1 h20.08
  text "G26" at 292.5,99.1 h20.08
  text "G23" at 142.5,99.1 h20.08
  text "G20" at -7.5,99.1 h20.08
  text "G17" at -157.5,99.1 h20.08
  text "G14" at -307.5,99.1 h20.08
  text "G11" at -457.5,99.1 h20.08
  text "G8" at -607.5,91.06 h20.08
  text "G4" at -807.5,91.06 h20.08
  text "G40" at 992.5,99.1 h20.08
  text "K18" at -107.5,249.1 h20.08
  text "K27" at 342.5,249.1 h20.08
  text "K39" at 942.5,249.1 h20.08
  text "K6" at -707.5,241.06 h20.08
  text "K15" at -257.5,249.1 h20.08
  text "K2" at -907.5,241.06 h20.08
  text "K3" at -857.5,241.06 h20.08
  text "K21" at 42.5,249.1 h20.08
  text "K36" at 792.5,249.1 h20.08
  text "K24" at 192.5,249.1 h20.08
  text "Z11" at -470.5,-221.81 h20.08
  text "Z10" at -520.5,-221.81 h20.08
  text "Z7" at -670.5,-237.87 h20.08
  text "Z6" at -720.5,-237.87 h20.08
  text "Z3" at -870.5,-237.87 h20.08
  text "Z2" at -920.5,-237.87 h20.08
  text "Z15" at -270.5,-221.81 h20.08
  text "Z14" at -320.5,-221.81 h20.08
  text "Z19" at -70.5,-221.81 h20.08
  text "Z18" at -120.5,-221.81 h20.08
  text "Z27" at 329.5,-221.81 h20.08
  text "Z26" at 279.5,-221.81 h20.08
  text "Z23" at 129.5,-221.81 h20.08
  text "Z22" at 79.5,-221.81 h20.08
  text "Z31" at 529.5,-221.81 h20.08
  text "Z30" at 479.5,-221.81 h20.08
  text "Z35" at 729.5,-221.81 h20.08
  text "Z34" at 679.5,-221.81 h20.08
  text "Z39" at 929.5,-221.81 h20.08
  text "Z38" at 879.5,-221.81 h20.08
  text "Y5" at -770.5,-287.87 h20.08
  text "Y9" at -570.5,-287.87 h20.08
  text "Y12" at -420.5,-271.81 h20.08
  text "Y13" at -370.5,-271.81 h20.08
  text "Y16" at -220.5,-271.81 h20.08
  text "Y17" at -170.5,-271.81 h20.08
  text "Y20" at -20.5,-271.81 h20.08
  text "Y21" at 29.5,-271.81 h20.08
  text "Y24" at 179.5,-271.81 h20.08
  text "Y25" at 229.5,-271.81 h20.08
  text "Y33" at 629.5,-271.81 h20.08
  text "Y32" at 579.5,-271.81 h20.08
  text "Y28" at 379.5,-271.81 h20.08
  text "Y29" at 429.5,-271.81 h20.08
  text "Y40" at 979.5,-271.81 h20.08
  text "Y36" at 779.5,-271.81 h20.08
  text "Y37" at 829.5,-271.81 h20.08
  text "Y4" at -820.5,-287.87 h20.08
  text "Y8" at -620.5,-287.87 h20.08
  text "Y1" at -970.5,-287.87 h20.08
  text "L15" at -257.5,299.1 h20.08
  text "L14" at -307.5,299.1 h20.08
  text "L11" at -457.5,299.1 h20.08
  text "L7" at -657.5,291.06 h20.08
  text "L6" at -707.5,291.06 h20.08
  text "L3" at -857.5,291.06 h20.08
  text "L2" at -907.5,291.06 h20.08
  text "L19" at -57.5,299.1 h20.08
  text "L18" at -107.5,299.1 h20.08
  text "L23" at 142.5,299.1 h20.08
  text "L22" at 92.5,299.1 h20.08
  text "L27" at 342.5,299.1 h20.08
  text "L26" at 292.5,299.1 h20.08
  text "L34" at 692.5,299.1 h20.08
  text "L38" at 892.5,299.1 h20.08
  text "L39" at 942.5,299.1 h20.08
  text "L35" at 742.5,299.1 h20.08
  text "M40" at 992.5,349.1 h20.08
  text "M37" at 842.5,349.1 h20.08
  text "M36" at 792.5,349.1 h20.08
  text "M32" at 592.5,349.1 h20.08
  text "M29" at 442.5,349.1 h20.08
  text "M28" at 392.5,349.1 h20.08
  text "M25" at 242.5,349.1 h20.08
  text "M24" at 192.5,349.1 h20.08
  text "M21" at 42.5,349.1 h20.08
  text "M20" at -7.5,349.1 h20.08
  text "M17" at -157.5,349.1 h20.08
  text "M16" at -207.5,349.1 h20.08
  text "M8" at -607.5,341.06 h20.08
  text "M5" at -757.5,341.06 h20.08
  text "M4" at -807.5,341.06 h20.08
  text "M1" at -957.5,341.06 h20.08
  text "M33" at 642.5,349.1 h20.08
  text "J32" at 592.5,199.1 h20.08
  text "K33" at 642.5,249.1 h20.08
  text "H33" at 642.5,149.1 h20.08
  text "G32" at 592.5,99.1 h20.08
  text "F33" at 642.5,49.1 h20.08
  text "E32" at 592.5,-0.9 h20.08
  text "F30" at 492.5,49.1 h20.08
  text "L30" at 492.5,299.1 h20.08
  text "K30" at 492.5,249.1 h20.08
  text "L31" at 542.5,299.1 h20.08
  text "H30" at 492.5,149.1 h20.08
  text "D13" at -357.5,-50.9 h20.08
  text "C13" at -357.5,-100.9 h20.08
  text "A13" at -357.5,-200.9 h20.08
  text "M9" at -557.5,341.06 h20.08
  text "K9" at -557.5,241.06 h20.08
  text "H9" at -557.5,141.06 h20.08
  text "A12" at -407.5,-200.9 h20.08
  text "F12" at -407.5,49.1 h20.08
  text "H12" at -407.5,149.1 h20.08
  text "K12" at -407.5,249.1 h20.08
  text "M12" at -407.5,349.1 h20.08
  text "M13" at -357.5,349.1 h20.08
  text "L10" at -507.5,299.1 h20.08
  text "Z9" at -570.5,-237.87 h20.08
  text "Z8" at -620.5,-237.87 h20.08
  text "Z5" at -770.5,-237.87 h20.08
  text "Z40" at 979.5,-221.81 h20.08
  text "Z4" at -820.5,-237.87 h20.08
  text "Z37" at 829.5,-221.81 h20.08
  text "Z36" at 779.5,-221.81 h20.08
  text "Z33" at 629.5,-221.81 h20.08
  text "Z32" at 579.5,-221.81 h20.08
  text "Z29" at 429.5,-221.81 h20.08
  text "Z28" at 379.5,-221.81 h20.08
  text "Z25" at 229.5,-221.81 h20.08
  text "Z24" at 179.5,-221.81 h20.08
  text "Y7" at -670.5,-287.87 h20.08
  text "Y6" at -720.5,-287.87 h20.08
  text "Y39" at 929.5,-271.81 h20.08
  text "Y38" at 879.5,-271.81 h20.08
  text "Y35" at 729.5,-271.81 h20.08
  text "Y34" at 679.5,-271.81 h20.08
  text "Y31" at 529.5,-271.81 h20.08
  text "Y30" at 479.5,-271.81 h20.08
  text "Y3" at -870.5,-287.87 h20.08
  text "Y27" at 329.5,-271.81 h20.08
  text "Y26" at 279.5,-271.81 h20.08
  text "Y2" at -920.5,-287.87 h20.08
  text "M7" at -657.5,341.06 h20.08
  text "M6" at -707.5,341.06 h20.08
  text "M39" at 942.5,349.1 h20.08
  text "M38" at 892.5,349.1 h20.08
  text "M35" at 742.5,349.1 h20.08
  text "M34" at 692.5,349.1 h20.08
  text "M31" at 542.5,349.1 h20.08
  text "M30" at 492.5,349.1 h20.08
  text "M3" at -857.5,341.06 h20.08
  text "M27" at 342.5,349.1 h20.08
  text "M26" at 292.5,349.1 h20.08
  text "M23" at 142.5,349.1 h20.08
  text "M22" at 92.5,349.1 h20.08
  text "M2" at -907.5,341.06 h20.08
  text "M19" at -57.5,349.1 h20.08
  text "M18" at -107.5,349.1 h20.08
  text "M15" at -257.5,349.1 h20.08
  text "M14" at -307.5,349.1 h20.08
  text "M11" at -457.5,349.1 h20.08
  text "M10" at -507.5,349.1 h20.08
  text "L9" at -557.5,291.06 h20.08
  text "L8" at -607.5,291.06 h20.08
  text "L5" at -757.5,291.06 h20.08
  text "L40" at 992.5,299.1 h20.08
  text "L4" at -807.5,291.06 h20.08
  text "L37" at 842.5,299.1 h20.08
  text "L36" at 792.5,299.1 h20.08
  text "L33" at 642.5,299.1 h20.08
  text "L32" at 592.5,299.1 h20.08
  text "L29" at 442.5,299.1 h20.08
  text "L28" at 392.5,299.1 h20.08
  text "L25" at 242.5,299.1 h20.08
  text "L24" at 192.5,299.1 h20.08
  text "L21" at 42.5,299.1 h20.08
  text "L20" at -7.5,299.1 h20.08
  text "L17" at -157.5,299.1 h20.08
  text "L16" at -207.5,299.1 h20.08
  text "L13" at -357.5,299.1 h20.08
  text "L12" at -407.5,299.1 h20.08
  text "L1" at -957.5,291.06 h20.08
  text "K8" at -607.5,241.06 h20.08
  text "K7" at -657.5,241.06 h20.08
  text "K5" at -757.5,241.06 h20.08
  text "K4" at -807.5,241.06 h20.08
  text "K38" at 892.5,249.1 h20.08
  text "K37" at 842.5,249.1 h20.08
  text "K35" at 742.5,249.1 h20.08
  text "K34" at 692.5,249.1 h20.08
  text "K32" at 592.5,249.1 h20.08
  text "K31" at 542.5,249.1 h20.08
  text "K29" at 442.5,249.1 h20.08
  text "K28" at 392.5,249.1 h20.08
  text "K26" at 292.5,249.1 h20.08
  text "K25" at 242.5,249.1 h20.08
  text "K23" at 142.5,249.1 h20.08
  text "K22" at 92.5,249.1 h20.08
  text "K20" at -7.5,249.1 h20.08
  text "K19" at -57.5,249.1 h20.08
  text "K17" at -157.5,249.1 h20.08
  text "K16" at -207.5,249.1 h20.08
  text "K14" at -307.5,249.1 h20.08
  text "K13" at -357.5,249.1 h20.08
  text "K11" at -457.5,249.1 h20.08
  text "K10" at -507.5,249.1 h20.08
  text "K1" at -957.5,241.06 h20.08
  text "J9" at -557.5,191.06 h20.08
  text "J7" at -657.5,191.06 h20.08
  text "J6" at -707.5,191.06 h20.08
  text "J37" at 842.5,199.1 h20.08
  text "J36" at 792.5,199.1 h20.08
  text "J34" at 692.5,199.1 h20.08
  text "J33" at 642.5,199.1 h20.08
  text "J31" at 542.5,199.1 h20.08
  text "J30" at 492.5,199.1 h20.08
  text "J3" at -857.5,191.06 h20.08
  text "J28" at 392.5,199.1 h20.08
  text "J27" at 342.5,199.1 h20.08
  text "J25" at 242.5,199.1 h20.08
  text "J24" at 192.5,199.1 h20.08
  text "J22" at 92.5,199.1 h20.08
  text "J21" at 42.5,199.1 h20.08
  text "J2" at -907.5,191.06 h20.08
  text "J19" at -57.5,199.1 h20.08
  text "J18" at -107.5,199.1 h20.08
  text "J16" at -207.5,199.1 h20.08
  text "J13" at -357.5,199.1 h20.08
  text "J12" at -407.5,199.1 h20.08
  text "J10" at -507.5,199.1 h20.08
  text "H8" at -607.5,141.06 h20.08
  text "H7" at -657.5,141.06 h20.08
  text "H5" at -757.5,141.06 h20.08
  text "H4" at -807.5,141.06 h20.08
  text "H38" at 892.5,149.1 h20.08
  text "H37" at 842.5,149.1 h20.08
  text "H35" at 742.5,149.1 h20.08
  text "H34" at 692.5,149.1 h20.08
  text "H32" at 592.5,149.1 h20.08
  text "H29" at 442.5,149.1 h20.08
  text "H28" at 392.5,149.1 h20.08
  text "H26" at 292.5,149.1 h20.08
  text "H25" at 242.5,149.1 h20.08
  text "H23" at 142.5,149.1 h20.08
  text "H22" at 92.5,149.1 h20.08
  text "H20" at -7.5,149.1 h20.08
  text "H19" at -57.5,149.1 h20.08
  text "H17" at -157.5,149.1 h20.08
  text "H16" at -207.5,149.1 h20.08
  text "H14" at -307.5,149.1 h20.08
  text "H13" at -357.5,149.1 h20.08
  text "H11" at -457.5,149.1 h20.08
  text "H10" at -507.5,149.1 h20.08
  text "H1" at -957.5,141.06 h20.08
  text "G37" at 842.5,99.1 h20.08
  text "G36" at 792.5,99.1 h20.08
  text "G34" at 692.5,99.1 h20.08
  text "G33" at 642.5,99.1 h20.08
  text "G31" at 542.5,99.1 h20.08
  text "G30" at 492.5,99.1 h20.08
  text "G3" at -857.5,91.06 h20.08
  text "G28" at 392.5,99.1 h20.08
  text "G25" at 242.5,99.1 h20.08
  text "G24" at 192.5,99.1 h20.08
  text "G22" at 92.5,99.1 h20.08
  text "G21" at 42.5,99.1 h20.08
  text "G2" at -907.5,91.06 h20.08
  text "G19" at -57.5,99.1 h20.08
  text "G18" at -107.5,99.1 h20.08
  text "G16" at -207.5,99.1 h20.08
  text "G15" at -257.5,99.1 h20.08
  text "F8" at -607.5,41.06 h20.08
  text "F7" at -657.5,41.06 h20.08
  text "F5" at -757.5,41.06 h20.08
  text "F4" at -807.5,41.06 h20.08
  text "F38" at 892.5,49.1 h20.08
  text "F37" at 842.5,49.1 h20.08
  text "F35" at 742.5,49.1 h20.08
  text "F34" at 692.5,49.1 h20.08
  text "F32" at 592.5,49.1 h20.08
  text "F31" at 542.5,49.1 h20.08
  text "F29" at 442.5,49.1 h20.08
  text "F28" at 392.5,49.1 h20.08
  text "F26" at 292.5,49.1 h20.08
  text "F25" at 242.5,49.1 h20.08
  text "F23" at 142.5,49.1 h20.08
  text "F22" at 92.5,49.1 h20.08
  text "F20" at -7.5,49.1 h20.08
  text "F19" at -57.5,49.1 h20.08
  text "F17" at -157.5,49.1 h20.08
  text "F16" at -207.5,49.1 h20.08
  text "F14" at -307.5,49.1 h20.08
  text "F13" at -357.5,49.1 h20.08
  text "F11" at -457.5,49.1 h20.08
  text "F10" at -507.5,49.1 h20.08
  text "E9" at -557.5,-8.94 h20.08
  text "E7" at -657.5,-8.94 h20.08
  text "E6" at -707.5,-8.94 h20.08
  text "E37" at 842.5,-0.9 h20.08
  text "E36" at 792.5,-0.9 h20.08
  text "E34" at 692.5,-0.9 h20.08
  text "E33" at 642.5,-0.9 h20.08
  text "E31" at 542.5,-0.9 h20.08
  text "E30" at 492.5,-0.9 h20.08
  text "E3" at -857.5,-8.94 h20.08
  text "E28" at 392.5,-0.9 h20.08
  text "E27" at 342.5,-0.9 h20.08
  text "E25" at 242.5,-0.9 h20.08
  text "E24" at 192.5,-0.9 h20.08
  text "E22" at 92.5,-0.9 h20.08
  text "E21" at 42.5,-0.9 h20.08
  text "E2" at -907.5,-8.94 h20.08
  text "E19" at -57.5,-0.9 h20.08
  text "E18" at -107.5,-0.9 h20.08
  text "E16" at -207.5,-0.9 h20.08
  text "E15" at -257.5,-0.9 h20.08
  text "E13" at -357.5,-0.9 h20.08
  text "E12" at -407.5,-0.9 h20.08
  text "E10" at -507.5,-0.9 h20.08
  text "D9" at -557.5,-58.94 h20.08
  text "D8" at -607.5,-58.94 h20.08
  text "D34" at 692.5,-50.9 h20.08
  text "D33" at 642.5,-50.9 h20.08
  text "D29" at 442.5,-50.9 h20.08
  text "D27" at 342.5,-50.9 h20.08
  text "D24" at 192.5,-50.9 h20.08
  text "D23" at 142.5,-50.9 h20.08
  text "D21" at 42.5,-50.9 h20.08
  text "D20" at -7.5,-50.9 h20.08
  text "D18" at -107.5,-50.9 h20.08
  text "D17" at -157.5,-50.9 h20.08
  text "D15" at -257.5,-50.9 h20.08
  text "D14" at -307.5,-50.9 h20.08
  text "D12" at -407.5,-50.9 h20.08
  text "D11" at -457.5,-50.9 h20.08
  text "C3" at -857.5,-108.94 h20.08
  text "C27" at 342.5,-100.9 h20.08
  text "C26" at 292.5,-100.9 h20.08
  text "C23" at 142.5,-100.9 h20.08
  text "C22" at 92.5,-100.9 h20.08
  text "C2" at -907.5,-108.94 h20.08
  text "C19" at -57.5,-100.9 h20.08
  text "C18" at -107.5,-100.9 h20.08
  text "C15" at -257.5,-100.9 h20.08
  text "C14" at -307.5,-100.9 h20.08
  text "C11" at -457.5,-100.9 h20.08
  text "C10" at -507.5,-100.9 h20.08
  text "B40" at 992.5,-150.9 h20.08
  text "B37" at 842.5,-150.9 h20.08
  text "B36" at 792.5,-150.9 h20.08
  text "B33" at 642.5,-150.9 h20.08
  text "B32" at 592.5,-150.9 h20.08
  text "B29" at 442.5,-150.9 h20.08
  text "B28" at 392.5,-150.9 h20.08
  text "B25" at 242.5,-150.9 h20.08
  text "B24" at 192.5,-150.9 h20.08
  text "B21" at 42.5,-150.9 h20.08
  text "B20" at -7.5,-150.9 h20.08
  text "B1" at -957.5,-158.94 h20.08
  text "A39" at 942.5,-200.9 h20.08
  text "A38" at 892.5,-200.9 h20.08
  text "A35" at 742.5,-200.9 h20.08
  text "A34" at 692.5,-200.9 h20.08
  text "A31" at 542.5,-200.9 h20.08
  text "A30" at 492.5,-200.9 h20.08
  text "A27" at 342.5,-200.9 h20.08
  text "A26" at 292.5,-200.9 h20.08
  text "A23" at 142.5,-200.9 h20.08
  text "A22" at 92.5,-200.9 h20.08

## CONN_PPPC042LFBN-RC [mm] "Sullins socket, 100 mil spacing, 4x2"
height 8.509
pads (8):
  rect 1.65x1.65 hole 1 mask+0: 1(0,0)
  round 1.65 hole 1 mask+0: 2(0,2.54) 3(-2.54,0) 4(-2.54,2.54) 5(-5.08,0.025) 6(-5.08,2.565) 7(-7.62,0.025) 8(-7.62,2.565)
Top Overlay:
  circle w0.25: c1.96,-0.263 r0.125
  lines w0.178: -9.14,-1.27 -9.14,3.81 1.52,3.81 1.52,-1.27 -9.14,-1.27
Mechanical 5:
  circle w0.25: c1.96,-0.263 r0.125
  lines w0.127: -9.14,-1.27 1.52,-1.27 ; -9.14,-1.27 -9.14,3.81 ; -9.14,-1.27 -9.14,3.81 ; -9.14,-1.27 1.52,-1.27 ; -9.14,3.81 1.52,3.81 ; -9.14,3.81 1.52,3.81 ; 1.52,-1.27 1.52,3.81 ; 1.52,-1.27 1.52,3.81
  text ".Designator" at -6.985,0.889 h1.02
3D body "Sullins_PPPC042LFBN-RC.stp": height 8.52, standoff -4.91, extent -9.14,-1.27 1.52,3.81

## Emerson_142-0701-851 [mil] "Johnson Components"
height 154
pads (5):
  rect 45x200 smd: 1(0,-110)
  rect 95x200 smd: 2(-172.5,-110) 3(172.5,-110)
  rect 95x200 smd far side: 4(172.5,-110) 5(-172.5,-110)
Top Overlay:
  lines w7: -235,0 -235,-220 -5,-220 235,-220 235,0
Mechanical 1:
  lines w3.94: -235,0 235,0
Mechanical 5:
  lines w5: -145,0 -145,-197 -190,-197 -190,0 ; -123.5,75 -108,90 ; -10,0 -10,-90 10,-90 10,0 ; 123.5,75 108,90 ; 145,0 145,-197 190,-197 190,0 ; -190,0 190,0 ; -190,0 -190,75 190,75 190,0 ; -123,173.9 -108,165.24 ; -123,173.9 -108,182.56 ; -123,173.9 0,173.9 123,173.9 ; -123,205.9 -108,214.56 ; -123,205.9 -108,197.24 ; -123,205.9 0,205.9 123,205.9 ; -123,237.9 -108,229.24 ; -123,237.9 -108,246.56 ; -123,237.9 0,237.9 123,237.9 ; -123,269.9 -108,278.56 ; -123,269.9 -108,261.24 ; -123,269.9 0,269.9 123,269.9 ; -123,301.9 -108,293.24 ; -123,301.9 -108,310.56 ; -123,301.9 0,301.9 123,301.9 ; -123,333.9 -108,325.24 ; -123,333.9 -108,342.56 ; -123,333.9 0,333.9 123,333.9 ; -108,90 -108,165.24 ; -108,90 108,90 ; -108,165.24 108,165.24 ; -108,182.56 -108,197.24 ; -108,182.56 108,182.56 ; -108,197.24 108,197.24 ; -108,214.56 -108,229.24 ; -108,214.56 108,214.56 ; -108,229.24 108,229.24 ; -108,246.56 -108,261.24 ; -108,246.56 108,246.56 ; -108,261.24 108,261.24 ; -108,278.56 -108,293.24 ; -108,278.56 108,278.56 ; -108,293.24 108,293.24 ; -108,310.56 -108,325.24 ; -108,310.56 108,310.56 ; -108,325.24 108,325.24 ; -108,342.56 -108,385 108,385 108,342.56 ; -108,342.56 108,342.56 ; 108,90 108,165.24 ; 108,165.24 123,173.9 ; 108,182.56 123,173.9 ; 108,182.56 108,197.24 ; 108,197.24 123,205.9 ; 108,214.56 123,205.9 ; 108,214.56 108,229.24 ; 108,229.24 123,237.9 ; 108,246.56 108,261.24 ; 108,246.56 123,237.9 ; 108,261.24 123,269.9 ; 108,278.56 108,293.24 ; 108,278.56 123,269.9 ; 108,293.24 123,301.9 ; 108,310.56 123,301.9 ; 108,310.56 108,325.24 ; 108,325.24 123,333.9 ; 108,342.56 123,333.9
  text ".Designator" at -100,-165 h40
3D body "Johnson_142-0701-851.stp": height 154.6, standoff -162.4, extent -190,-195 190,387

## FCC_disclaimer [mil]
height 375.2
Top Overlay:
  text "For evaluation only; not FCC approved for resale." at -627.08,-13.9 h60

## Fiducial10-20 [mm]
height 9.53
pads (1):
  round 1 smd mask+0.5: 1(0,0)
Top Layer keep-out:
  circle w1.178: c0,0 r0.5

## Keystone_1902C [mil] "Hex Standoff, 4-40 threaded, nylon"
height 500
pads (1):
  round 1 on Mech3: 0(0,0)
Mechanical 5:
  lines w5: -145.29,0.49 -72.56,126.47 72.92,126.47 145.65,0.49 72.92,-125.49 -72.56,-125.49 -145.29,0.49
  text ".Designator" at -60,-20 h40
3D body "Keystone_1902C.stp": height 501, standoff 1, extent -144.95,-125.98 146,125.98

## Label_650x200 [mil] "Thermal Transfer Label"
height 1
pads (1):
  round 1 on Mech13: 0(0,0)
Top Overlay:
  lines w5: -325,-75 ccw(c-300,-75) -300,-100 300,-100 ccw(c300,-75) 325,-75 325,75 ccw(c300,75) 300,100 -300,100 ccw(c-300,75) -325,75 -325,-75
Mechanical 5:
  lines w5: -325,-75 ccw(c-300,-75) -300,-100 300,-100 ccw(c300,-75) 325,-75 325,75 ccw(c300,75) 300,100 -300,100 ccw(c-300,75) -325,75 -325,-75
  text ".Designator" at -60,-20 h40
3D body: height 1, standoff 0, extent -325.02,-100.02 325.02,100.02

## NY PMS 440 0025 PH [mm] "4-40 nylon screw and mounting hole"
height 1.905
pads (1):
  round 8 hole 3.2: 1(0,0)
Mechanical 5:
  circle w0.127: c0,0 r3.789
  text ".Designator" at -1.524,-0.508 h1.02
3D body "B_F_NY PMS 440 0025 PH.stp": height 2.69, standoff -8.74, extent -3.302,-3.3 3.296,3.3

## Pb-Free_Overlay_Small [mil]
height 375.2
Top Overlay:
  circle w8: c0,0 r46
  lines w8: -32.53,32.53 32.53,-32.53
  text "Pb" at -29.6,-18.9 h60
